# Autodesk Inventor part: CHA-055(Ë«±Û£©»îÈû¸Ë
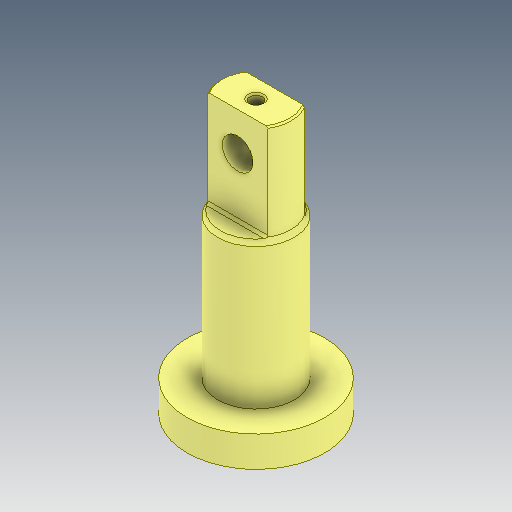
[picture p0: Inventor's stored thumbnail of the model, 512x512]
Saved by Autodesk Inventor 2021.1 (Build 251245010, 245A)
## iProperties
Created: 2021-05
Part Number: CHA-055(Ë«±Û£©»îÈû¸Ë
Material: Ogólny
Document SubType Name: Modeling
Designer: user
Density: 1 g/cm^3
Appearance: Domyślna
Author: user
Revision Number: ÈÎºÎ
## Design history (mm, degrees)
feature "ÊäÈë1"
node "Bryła1"
